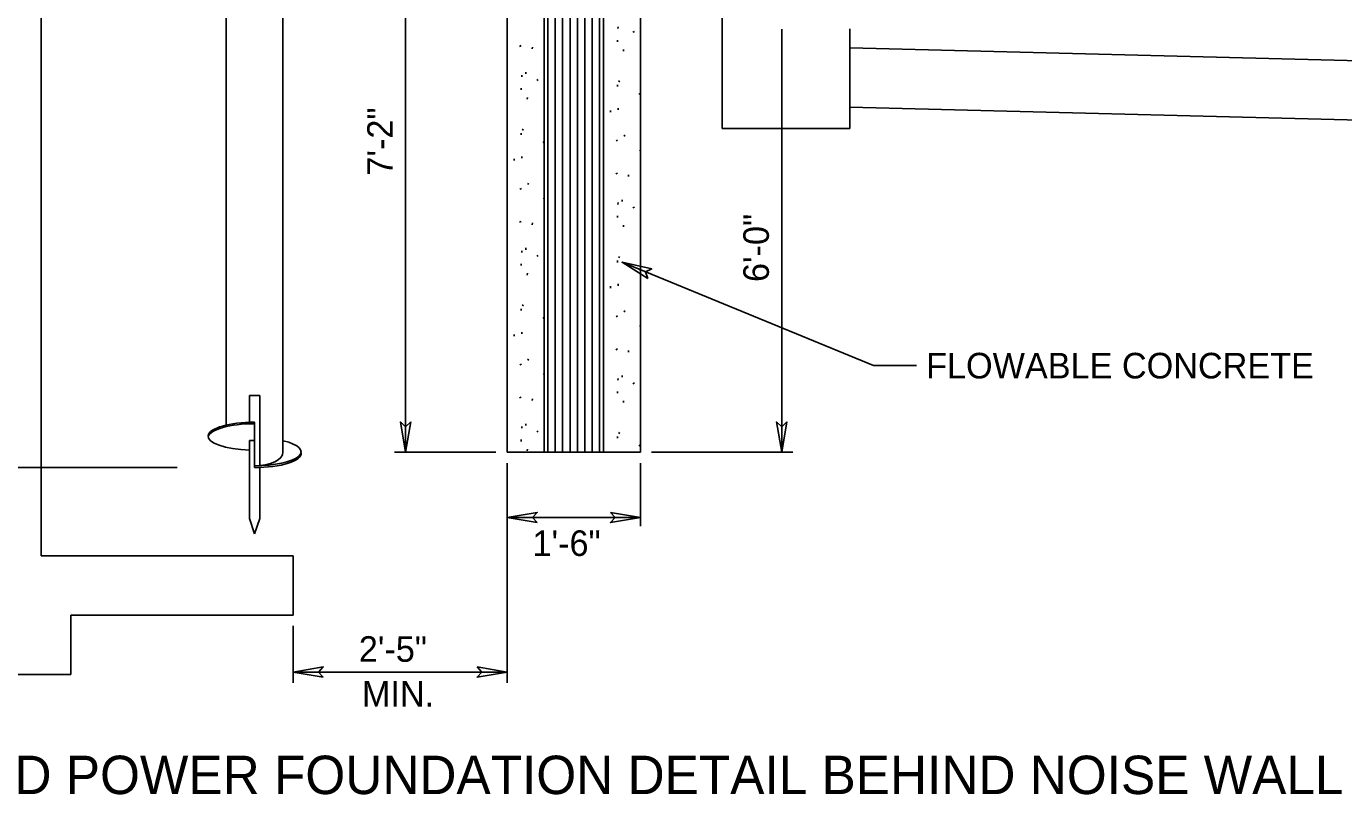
# Model space of a CAD drawing. Extents: x 99836 to 115004, y 99786 to 102182.
# Drawn here: x 114076 to 114694, y 100452 to 100812 of the extents above; entities that cross this region are included whole.
import ezdxf

# ---------------------------------------------------------------- set-up
doc = ezdxf.new("R2010")
doc.units = 0
doc.layers.add('Border Organizer Shape', color=7, linetype='Continuous')

msp = doc.modelspace()

# ---------------------------------------------------------------- linework, layer by layer
at = {"layer": 'Border Organizer Shape'}
for p, q in [((114319.06, 100612.67), (114319.06, 101467.55)), ((114320.75, 100612.67), (114320.75, 101411.95)), ((114324.23, 100612.67), (114324.23, 101411.95)), ((114327.7, 100612.67), (114327.7, 101411.95)), ((114331.18, 100612.67), (114331.18, 101411.95)), ((114334.65, 100612.67), (114334.65, 101411.95)), ((114338.13, 100612.67), (114338.13, 101411.95)), ((114341.6, 100612.67), (114341.6, 101411.95)), ((114345.08, 100612.67), (114345.08, 101411.95)), ((114346.86, 100612.67), (114346.86, 101022.73)), ((114319.06, 100617.88), (114319.06, 100990.82)), ((114319.06, 100617.67), (114319.06, 100962.96)), ((114169.95, 100625.32), (114169.95, 100914.7)), ((114196.59, 100612.67), (114196.59, 100914.7)), ((114083.19, 100564.02), (114083.19, 100911.53)), ((114254.09, 100910.56), (114254.09, 100612.67)), ((114301.69, 100612.67), (114301.69, 100862.88)), ((114364.24, 100612.67), (114364.24, 100862.11)), ((114402.47, 100764.31), (114402.47, 100822.2)), ((114353.7, 100811.93), (114353.65, 100811.12)), ((114360.67, 100809.43), (114361.42, 100809.79)), ((114430.45, 100612.67), (114430.45, 100810.82)), ((114462.41, 100764.31), (114462.41, 100811.1)), ((114307.52, 100802.8), (114308.27, 100803.16)), ((114353.45, 100805.79), (114353.4, 100804.98)), ((114313.54, 100802.41), (114313.5, 100801.6)), ((114356.32, 100801.38), (114356.28, 100800.58)), ((114744.9, 100795.01), (114462.41, 100802.18)), ((114310.51, 100790.69), (114310.47, 100789.89)), ((114308.57, 100789.36), (114308.53, 100788.55)), ((114315.55, 100786.86), (114316.3, 100787.22)), ((114353.45, 100784.74), (114353.4, 100783.94)), ((114354.49, 100786.16), (114353.85, 100786.59)), ((114308.32, 100783.21), (114308.28, 100782.41)), ((114311.2, 100778.81), (114311.16, 100778)), ((114363.52, 100780.38), (114364.24, 100780.73)), ((114350.14, 100772.72), (114350.1, 100771.91)), ((114353.74, 100773.82), (114353.7, 100773.01)), ((114756.36, 100766.91), (114462.41, 100774.38)), ((114308.32, 100762.17), (114308.28, 100761.36)), ((114309.37, 100763.59), (114308.73, 100764.02)), ((114357.07, 100760.74), (114356.43, 100761.18)), ((114462.41, 100764.31), (114402.47, 100764.31)), ((114318.4, 100757.8), (114319.06, 100758.12)), ((114352.77, 100758.47), (114353.52, 100758.83)), ((114363.79, 100753.91), (114364.24, 100754.13)), ((114305.02, 100750.14), (114304.98, 100749.34)), ((114308.62, 100751.24), (114308.57, 100750.44)), ((114352.64, 100743.01), (114353.39, 100743.37)), ((114358.66, 100742.62), (114358.62, 100741.82)), ((114307.64, 100735.9), (114308.39, 100736.26)), ((114311.95, 100738.16), (114311.31, 100738.61)), ((114318.67, 100731.34), (114319.06, 100731.52)), ((114353.7, 100729.57), (114353.65, 100728.77)), ((114355.63, 100730.91), (114355.59, 100730.1)), ((114353.45, 100723.43), (114353.4, 100722.62)), ((114360.67, 100727.07), (114361.42, 100727.43)), ((114307.52, 100720.44), (114308.27, 100720.8)), ((114313.54, 100720.05), (114313.5, 100719.24)), ((114356.32, 100719.02), (114356.28, 100718.21)), ((114308.57, 100707), (114308.53, 100706.19)), ((114310.51, 100708.33), (114310.47, 100707.52)), ((114315.55, 100704.49), (114316.3, 100704.86)), ((114354.49, 100703.8), (114353.85, 100704.23)), ((114308.32, 100700.85), (114308.28, 100700.05)), ((114353.45, 100702.38), (114353.4, 100701.58)), ((114355.58, 100701.67), (114473.5, 100653.18)), ((114363.52, 100698.02), (114364.24, 100698.36)), ((114311.2, 100696.45), (114311.16, 100695.64)), ((114350.14, 100690.36), (114350.1, 100689.55)), ((114353.74, 100691.46), (114353.7, 100690.65)), ((114308.32, 100679.81), (114308.28, 100679)), ((114309.37, 100681.23), (114308.73, 100681.66)), ((114318.4, 100675.44), (114319.06, 100675.76)), ((114352.77, 100676.11), (114353.52, 100676.47)), ((114357.07, 100678.38), (114356.43, 100678.82)), ((114305.02, 100667.78), (114304.98, 100666.98)), ((114308.62, 100668.88), (114308.57, 100668.08)), ((114363.79, 100671.55), (114364.24, 100671.77)), ((114352.64, 100660.65), (114353.39, 100661.01)), ((114311.95, 100655.8), (114311.31, 100656.25)), ((114358.66, 100660.26), (114358.62, 100659.46)), ((114307.64, 100653.54), (114308.39, 100653.9)), ((114318.67, 100648.98), (114319.06, 100649.16)), ((114355.63, 100648.54), (114355.59, 100647.74)), ((114473.5, 100653.18), (114493.7, 100653.18)), ((114353.7, 100647.21), (114353.65, 100646.4)), ((114360.67, 100644.71), (114361.42, 100645.07)), ((114180.85, 100639.18), (114185.69, 100639.18)), ((114180.85, 100639.18), (114180.85, 100626.65)), ((114185.69, 100639.18), (114185.69, 100606.45)), ((114307.52, 100638.08), (114308.27, 100638.44)), ((114313.54, 100637.69), (114313.5, 100636.88)), ((114353.45, 100641.07), (114353.4, 100640.26)), ((114356.32, 100636.66), (114356.28, 100635.85)), ((114183.27, 100626.69), (114183.27, 100605.42)), ((114308.57, 100624.64), (114308.53, 100623.83)), ((114310.51, 100625.97), (114310.47, 100625.16)), ((114180.85, 100618.13), (114180.85, 100581.53)), ((114180.85, 100618.13), (114183.27, 100618.13)), ((114308.32, 100618.49), (114308.28, 100617.69)), ((114315.55, 100622.13), (114316.3, 100622.5)), ((114353.45, 100620.02), (114353.4, 100619.22)), ((114354.49, 100621.44), (114353.85, 100621.87)), ((114296.47, 100612.67), (114248.88, 100612.67)), ((114301.69, 100612.67), (114364.24, 100612.67)), ((114311.2, 100614.09), (114311.16, 100613.28)), ((114319.06, 100612.67), (114346.86, 100612.67)), ((114363.52, 100615.66), (114364.24, 100616)), ((114369.45, 100612.67), (114435.67, 100612.67)), ((114147.01, 100605.43), (113748.05, 100605.43)), ((114185.69, 100605.38), (114185.69, 100581.53)), ((114301.69, 100607.46), (114301.69, 100576.77)), ((114364.24, 100607.46), (114364.24, 100578)), ((114180.85, 100581.53), (114183.27, 100574.29)), ((114185.69, 100581.53), (114183.27, 100574.29)), ((114301.69, 100581.98), (114364.24, 100581.98)), ((114301.69, 100576.94), (114301.69, 100504.54)), ((114083.19, 100564.02), (114201.34, 100564.02)), ((114201.34, 100536.22), (114201.34, 100564.02)), ((114097.09, 100508.41), (114097.09, 100536.22)), ((114097.09, 100536.22), (114201.34, 100536.22)), ((114201.34, 100531.18), (114201.34, 100504.54)), ((114069.29, 100508.41), (114097.09, 100508.41)), ((114301.69, 100509.57), (114201.34, 100509.57))]:
    msp.add_line(p, q, dxfattribs=at)
for points in [[(114319.06, 101411.95), (114346.86, 101411.95), (114346.86, 100612.67), (114319.06, 100612.67)], [(114367.71, 100694.09), (114355.58, 100701.67), (114369.53, 100698.52), (114366.57, 100697.15)], [(114256.49, 100626.77), (114254.09, 100612.67), (114251.7, 100626.77), (114254.09, 100624.55)], [(114432.85, 100626.77), (114430.45, 100612.67), (114428.06, 100626.77), (114430.45, 100624.55)], [(114315.79, 100579.59), (114301.69, 100581.98), (114315.79, 100584.38), (114313.57, 100581.98)], [(114350.14, 100584.38), (114364.24, 100581.98), (114350.14, 100579.59), (114352.35, 100581.98)], [(114215.44, 100507.18), (114201.34, 100509.57), (114215.44, 100511.97), (114213.23, 100509.57)], [(114287.58, 100511.97), (114301.69, 100509.57), (114287.58, 100507.18), (114289.8, 100509.57)]]:
    msp.add_lwpolyline(points, close=True, dxfattribs=at)
for centre, major_axis, ratio, start_param, end_param in [((114183.39, 100620.12), (21.98, 0), 0.298969, 1.579309, 4.602023), ((114183.39, 100619.4), (21.98, 0), 0.298969, 1.576397, 3.062958), ((114183.08, 100612.79), (-21.98, 0), 0.298969, 1.576478, 4.042496), ((114183.26, 100612.65), (13.33, 0.02), 0.482136, 4.712389, 6.283185), ((114183.16, 100612), (-21.98, 0), 0.298969, 1.576478, 3.180482)]:
    msp.add_ellipse(centre, major_axis=major_axis, ratio=ratio, start_param=start_param, end_param=end_param, dxfattribs=at)

# ---------------------------------------------------------------- texts
for s, p in [('7\'-2"', (114248.09, 100742.25)), ('6\'-0"', (114424.45, 100692.38))]:
    msp.add_text(s, height=12, rotation=90, dxfattribs=at).set_placement(p)
for s, height, p in [(' FLOWABLE CONCRETE', 12, (114493.7, 100647.18)), ('1\'-6"', 12, (114313.6, 100563.98)), ('2\'-5"', 12, (114232.15, 100514.37)), ('MIN.', 12, (114233.6, 100493.37)), ('TYPICAL POLE AND POWER FOUNDATION DETAIL BEHIND NOISE WALL', 18, (113859.31, 100452.37))]:
    msp.add_text(s, height=height, dxfattribs=at).set_placement(p)

doc.saveas('drawing.dxf')
